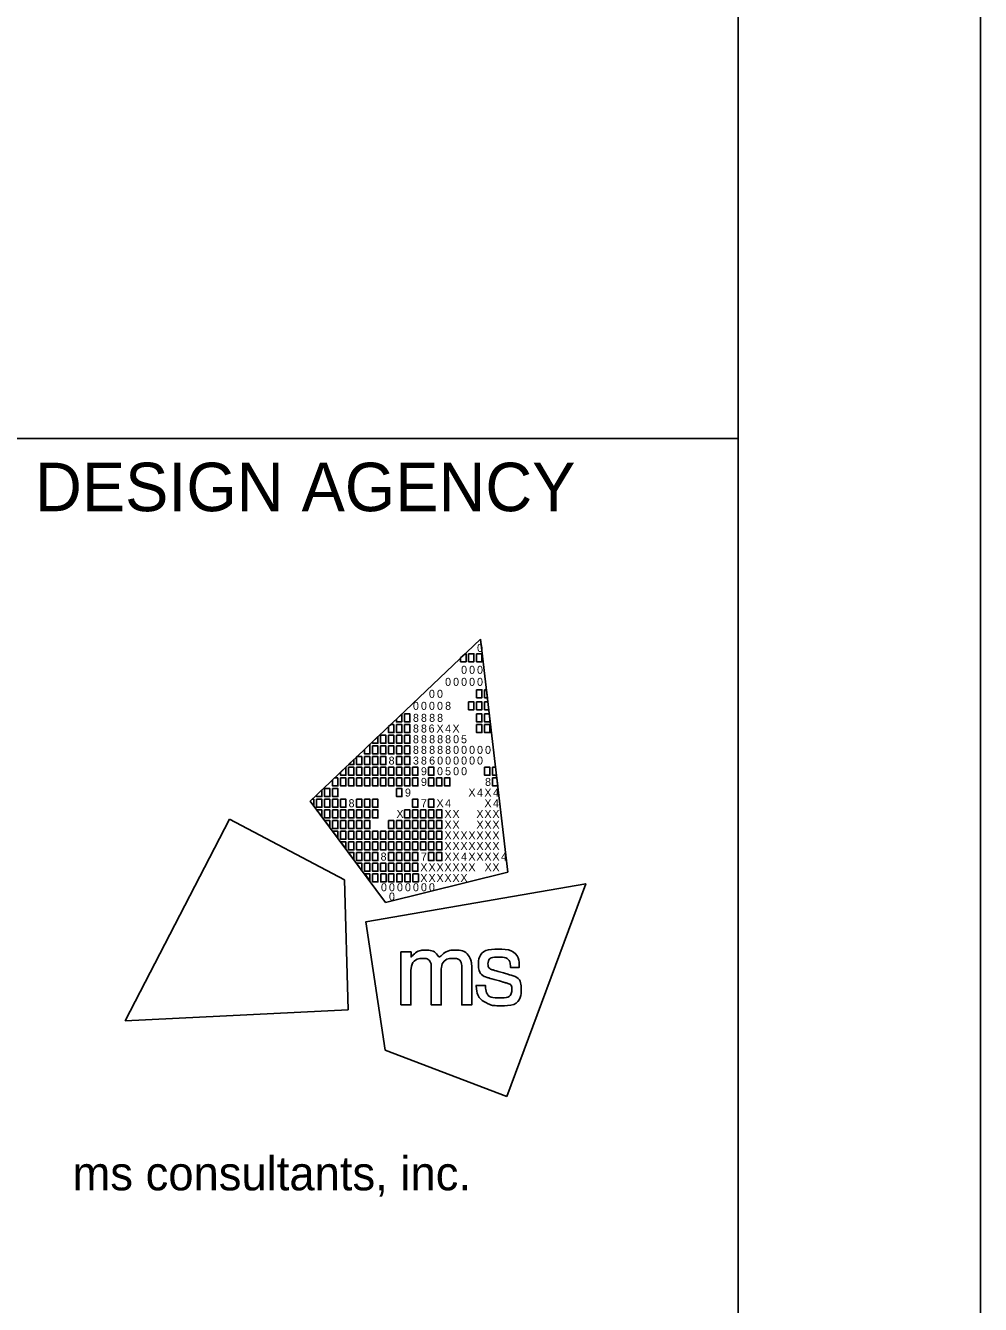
# Model space of a CAD drawing. Extents: x 0 to 65, y -0.7 to 22.
# Drawn here: x 32.03 to 34, y 2.714 to 5.352 of the extents above; entities that cross this region are included whole.
import ezdxf

# ---------------------------------------------------------------- set-up
doc = ezdxf.new("R2010")
doc.units = 0
for name, color, linetype in [('Default', 7, 'Continuous'), ('SH_Border', 7, 'Continuous'), ('SH_Cut_Line', 7, 'Continuous'), ('SH_Text', 7, 'Continuous')]:
    doc.layers.add(name, color=color, linetype=linetype)

msp = doc.modelspace()

# ---------------------------------------------------------------- linework, layer by layer
at = {"layer": 'Default'}
for p, q in [((32.6176, 3.7519), (32.9688, 4.0861)), ((32.9688, 4.0861), (32.9688, 4.0861)), ((32.9688, 4.0861), (33.0253, 3.6052)), ((32.773, 3.543), (32.6176, 3.7519)), ((33.0253, 3.6052), (32.773, 3.543))]:
    msp.add_line(p, q, dxfattribs=at)
for points in [[(32.9279, 4.0472), (32.9369, 4.0558), (32.939, 4.0558), (32.939, 4.0393), (32.9279, 4.0393)], [(32.9444, 4.0558), (32.9554, 4.0558), (32.9554, 4.0393), (32.9444, 4.0393)], [(32.9609, 4.0558), (32.9719, 4.0558), (32.9719, 4.0393), (32.9609, 4.0393)], [(32.9606, 3.9815), (32.9716, 3.9815), (32.9716, 3.965), (32.9606, 3.965)], [(32.9771, 3.9815), (32.9811, 3.9815), (32.983, 3.965), (32.9771, 3.965)], [(32.7954, 3.9211), (32.8064, 3.9316), (32.8064, 3.9154), (32.7954, 3.9154)], [(32.8123, 3.9319), (32.8233, 3.9319), (32.8233, 3.9154), (32.8123, 3.9154)], [(32.9442, 3.9567), (32.9552, 3.9567), (32.9552, 3.9402), (32.9442, 3.9402)], [(32.9606, 3.9567), (32.9716, 3.9567), (32.9716, 3.9402), (32.9606, 3.9402)], [(32.9606, 3.9319), (32.9716, 3.9319), (32.9716, 3.9154), (32.9606, 3.9154)], [(32.9771, 3.9567), (32.984, 3.9567), (32.9859, 3.9402), (32.9771, 3.9402)], [(32.9771, 3.9319), (32.9869, 3.9319), (32.9881, 3.9218), (32.9881, 3.9154), (32.9771, 3.9154)], [(32.7958, 3.9099), (32.8068, 3.9099), (32.8068, 3.8934), (32.7958, 3.8934)], [(32.8123, 3.9099), (32.8233, 3.9099), (32.8233, 3.8934), (32.8123, 3.8934)], [(32.9606, 3.9099), (32.9716, 3.9099), (32.9716, 3.8934), (32.9606, 3.8934)], [(32.9771, 3.9099), (32.9881, 3.9099), (32.9881, 3.8934), (32.9771, 3.8934)], [(32.7628, 3.8879), (32.7738, 3.8879), (32.7738, 3.8714), (32.7628, 3.8714)], [(32.7793, 3.8879), (32.7903, 3.8879), (32.7903, 3.8714), (32.7793, 3.8714)], [(32.7958, 3.8879), (32.8068, 3.8879), (32.8068, 3.8714), (32.7958, 3.8714)], [(32.8123, 3.8879), (32.8233, 3.8879), (32.8233, 3.8714), (32.8123, 3.8714)], [(32.7463, 3.8659), (32.7573, 3.8659), (32.7573, 3.8494), (32.7463, 3.8494)], [(32.7628, 3.8659), (32.7738, 3.8659), (32.7738, 3.8494), (32.7628, 3.8494)], [(32.7793, 3.8659), (32.7903, 3.8659), (32.7903, 3.8494), (32.7793, 3.8494)], [(32.7958, 3.8659), (32.8068, 3.8659), (32.8068, 3.8494), (32.7958, 3.8494)], [(32.8123, 3.8659), (32.8233, 3.8659), (32.8233, 3.8494), (32.8123, 3.8494)], [(32.7297, 3.8439), (32.7407, 3.8439), (32.7407, 3.8273), (32.7297, 3.8273)], [(32.7463, 3.8439), (32.7573, 3.8439), (32.7573, 3.8273), (32.7463, 3.8273)], [(32.7628, 3.8439), (32.7738, 3.8439), (32.7738, 3.8273), (32.7628, 3.8273)], [(32.7958, 3.8439), (32.8068, 3.8439), (32.8068, 3.8273), (32.7958, 3.8273)], [(32.8123, 3.8439), (32.8233, 3.8439), (32.8233, 3.8273), (32.8123, 3.8273)], [(32.6802, 3.7998), (32.6912, 3.7998), (32.6912, 3.7833), (32.6802, 3.7833)], [(32.6967, 3.8218), (32.7077, 3.8218), (32.7077, 3.8053), (32.6967, 3.8053)], [(32.6967, 3.7998), (32.7077, 3.7998), (32.7077, 3.7833), (32.6967, 3.7833)], [(32.7132, 3.8218), (32.7242, 3.8218), (32.7242, 3.8053), (32.7132, 3.8053)], [(32.7132, 3.7998), (32.7242, 3.7998), (32.7242, 3.7833), (32.7132, 3.7833)], [(32.7297, 3.8218), (32.7407, 3.8218), (32.7407, 3.8053), (32.7297, 3.8053)], [(32.7297, 3.7998), (32.7407, 3.7998), (32.7407, 3.7833), (32.7297, 3.7833)], [(32.7463, 3.8218), (32.7573, 3.8218), (32.7573, 3.8053), (32.7463, 3.8053)], [(32.7463, 3.7998), (32.7573, 3.7998), (32.7573, 3.7833), (32.7463, 3.7833)], [(32.7628, 3.8218), (32.7738, 3.8218), (32.7738, 3.8053), (32.7628, 3.8053)], [(32.7628, 3.7998), (32.7738, 3.7998), (32.7738, 3.7833), (32.7628, 3.7833)], [(32.7793, 3.8218), (32.7903, 3.8218), (32.7903, 3.8053), (32.7793, 3.8053)], [(32.7793, 3.7998), (32.7903, 3.7998), (32.7903, 3.7833), (32.7793, 3.7833)], [(32.7958, 3.8218), (32.8068, 3.8218), (32.8068, 3.8053), (32.7958, 3.8053)], [(32.7958, 3.7998), (32.8068, 3.7998), (32.8068, 3.7833), (32.7958, 3.7833)], [(32.8123, 3.8218), (32.8233, 3.8218), (32.8233, 3.8053), (32.8123, 3.8053)], [(32.8123, 3.7998), (32.8233, 3.7998), (32.8233, 3.7833), (32.8123, 3.7833)], [(32.8288, 3.8218), (32.8398, 3.8218), (32.8398, 3.8053), (32.8288, 3.8053)], [(32.8288, 3.7998), (32.8398, 3.7998), (32.8398, 3.7833), (32.8288, 3.7833)], [(32.8618, 3.8218), (32.8729, 3.8218), (32.8729, 3.8053), (32.8618, 3.8053)], [(32.8618, 3.7998), (32.8729, 3.7998), (32.8729, 3.7833), (32.8618, 3.7833)], [(32.8784, 3.7998), (32.8894, 3.7998), (32.8894, 3.7833), (32.8784, 3.7833)], [(32.8947, 3.7998), (32.9057, 3.7998), (32.9057, 3.7833), (32.8947, 3.7833)], [(32.9771, 3.8218), (32.9881, 3.8218), (32.9881, 3.8053), (32.9771, 3.8053)], [(32.9936, 3.8218), (32.9999, 3.8218), (33.0018, 3.8053), (32.9936, 3.8053)], [(32.9936, 3.7998), (33.0024, 3.7998), (33.0044, 3.7833), (32.9936, 3.7833)], [(32.6472, 3.7778), (32.6582, 3.7778), (32.6582, 3.7613), (32.6472, 3.7613)], [(32.6637, 3.7778), (32.6747, 3.7778), (32.6747, 3.7613), (32.6637, 3.7613)], [(32.7958, 3.7778), (32.8068, 3.7778), (32.8068, 3.7613), (32.7958, 3.7613)], [(32.6307, 3.7558), (32.6417, 3.7558), (32.6417, 3.7393), (32.6307, 3.7393)], [(32.6472, 3.7558), (32.6582, 3.7558), (32.6582, 3.7393), (32.6472, 3.7393)], [(32.6637, 3.7558), (32.6747, 3.7558), (32.6747, 3.7393), (32.6637, 3.7393)], [(32.6802, 3.7558), (32.6912, 3.7558), (32.6912, 3.7393), (32.6802, 3.7393)], [(32.7132, 3.7558), (32.7242, 3.7558), (32.7242, 3.7393), (32.7132, 3.7393)], [(32.7297, 3.7558), (32.7407, 3.7558), (32.7407, 3.7393), (32.7297, 3.7393)], [(32.7463, 3.7558), (32.7573, 3.7558), (32.7573, 3.7393), (32.7463, 3.7393)], [(32.8288, 3.7558), (32.8398, 3.7558), (32.8398, 3.7393), (32.8288, 3.7393)], [(32.8618, 3.7558), (32.8729, 3.7558), (32.8729, 3.7393), (32.8618, 3.7393)], [(32.6307, 3.7338), (32.6417, 3.7338), (32.6417, 3.72)], [(32.6472, 3.7338), (32.6582, 3.7338), (32.6582, 3.7173), (32.6472, 3.7173)], [(32.6637, 3.7338), (32.6747, 3.7338), (32.6747, 3.7173), (32.6637, 3.7173)], [(32.6802, 3.7338), (32.6912, 3.7338), (32.6912, 3.7173), (32.6802, 3.7173)], [(32.6967, 3.7338), (32.7077, 3.7338), (32.7077, 3.7173), (32.6967, 3.7173)], [(32.7132, 3.7338), (32.7242, 3.7338), (32.7242, 3.7173), (32.7132, 3.7173)], [(32.7297, 3.7338), (32.7407, 3.7338), (32.7407, 3.7173), (32.7297, 3.7173)], [(32.7463, 3.7338), (32.7573, 3.7338), (32.7573, 3.7173), (32.7463, 3.7173)], [(32.8123, 3.7338), (32.8233, 3.7338), (32.8233, 3.7173), (32.8123, 3.7173)], [(32.8288, 3.7338), (32.8398, 3.7338), (32.8398, 3.7173), (32.8288, 3.7173)], [(32.8453, 3.7338), (32.8563, 3.7338), (32.8563, 3.7173), (32.8453, 3.7173)], [(32.8618, 3.7338), (32.8729, 3.7338), (32.8729, 3.7173), (32.8618, 3.7173)], [(32.8784, 3.7338), (32.8894, 3.7338), (32.8894, 3.7173), (32.8784, 3.7173)], [(32.6472, 3.7117), (32.6582, 3.7117), (32.6582, 3.698)], [(32.6637, 3.7117), (32.6747, 3.7117), (32.6747, 3.6952), (32.6637, 3.6952)], [(32.6802, 3.7117), (32.6912, 3.7117), (32.6912, 3.6952), (32.6802, 3.6952)], [(32.6967, 3.7117), (32.7077, 3.7117), (32.7077, 3.6952), (32.6967, 3.6952)], [(32.7132, 3.7117), (32.7242, 3.7117), (32.7242, 3.6952), (32.7132, 3.6952)], [(32.7297, 3.7117), (32.7407, 3.7117), (32.7407, 3.6952), (32.7297, 3.6952)], [(32.7793, 3.7117), (32.7903, 3.7117), (32.7903, 3.6952), (32.7793, 3.6952)], [(32.7958, 3.7117), (32.8068, 3.7117), (32.8068, 3.6952), (32.7958, 3.6952)], [(32.8123, 3.7117), (32.8233, 3.7117), (32.8233, 3.6952), (32.8123, 3.6952)], [(32.8288, 3.7117), (32.8398, 3.7117), (32.8398, 3.6952), (32.8288, 3.6952)], [(32.8453, 3.7117), (32.8563, 3.7117), (32.8563, 3.6952), (32.8453, 3.6952)], [(32.8618, 3.7117), (32.8729, 3.7117), (32.8729, 3.6952), (32.8618, 3.6952)], [(32.8784, 3.7117), (32.8894, 3.7117), (32.8894, 3.6952), (32.8784, 3.6952)], [(32.6637, 3.6897), (32.6747, 3.6897), (32.6747, 3.676)], [(32.6747, 3.6897), (32.6747, 3.6897), (32.6747, 3.6897)], [(32.6802, 3.6897), (32.6912, 3.6897), (32.6912, 3.6732), (32.6802, 3.6732)], [(32.6802, 3.6677), (32.6912, 3.6677), (32.6912, 3.654)], [(32.6967, 3.6897), (32.7077, 3.6897), (32.7077, 3.6732), (32.6967, 3.6732)], [(32.6967, 3.6677), (32.7077, 3.6677), (32.7077, 3.6512), (32.6967, 3.6512)], [(32.7132, 3.6897), (32.7242, 3.6897), (32.7242, 3.6732), (32.7132, 3.6732)], [(32.7132, 3.6677), (32.7242, 3.6677), (32.7242, 3.6512), (32.7132, 3.6512)], [(32.7297, 3.6897), (32.7407, 3.6897), (32.7407, 3.6732), (32.7297, 3.6732)], [(32.7297, 3.6677), (32.7407, 3.6677), (32.7407, 3.6512), (32.7297, 3.6512)], [(32.7463, 3.6897), (32.7573, 3.6897), (32.7573, 3.6732), (32.7463, 3.6732)], [(32.7463, 3.6677), (32.7573, 3.6677), (32.7573, 3.6512), (32.7463, 3.6512)], [(32.7628, 3.6897), (32.7738, 3.6897), (32.7738, 3.6732), (32.7628, 3.6732)], [(32.7628, 3.6677), (32.7738, 3.6677), (32.7738, 3.6512), (32.7628, 3.6512)], [(32.7793, 3.6897), (32.7903, 3.6897), (32.7903, 3.6732), (32.7793, 3.6732)], [(32.7793, 3.6677), (32.7903, 3.6677), (32.7903, 3.6512), (32.7793, 3.6512)], [(32.7958, 3.6897), (32.8068, 3.6897), (32.8068, 3.6732), (32.7958, 3.6732)], [(32.7958, 3.6677), (32.8068, 3.6677), (32.8068, 3.6512), (32.7958, 3.6512)], [(32.8123, 3.6897), (32.8233, 3.6897), (32.8233, 3.6732), (32.8123, 3.6732)], [(32.8123, 3.6677), (32.8233, 3.6677), (32.8233, 3.6512), (32.8123, 3.6512)], [(32.8288, 3.6897), (32.8398, 3.6897), (32.8398, 3.6732), (32.8288, 3.6732)], [(32.8288, 3.6677), (32.8398, 3.6677), (32.8398, 3.6512), (32.8288, 3.6512)], [(32.8453, 3.6897), (32.8563, 3.6897), (32.8563, 3.6732), (32.8453, 3.6732)], [(32.8453, 3.6677), (32.8563, 3.6677), (32.8563, 3.6512), (32.8453, 3.6512)], [(32.8618, 3.6897), (32.8729, 3.6897), (32.8729, 3.6732), (32.8618, 3.6732)], [(32.8618, 3.6677), (32.8729, 3.6677), (32.8729, 3.6512), (32.8618, 3.6512)], [(32.8784, 3.6897), (32.8894, 3.6897), (32.8894, 3.6732), (32.8784, 3.6732)], [(32.8784, 3.6677), (32.8894, 3.6677), (32.8894, 3.6512), (32.8784, 3.6512)], [(32.7078, 3.6305), (32.6966, 3.6457), (32.7078, 3.6457)], [(32.7132, 3.6457), (32.7242, 3.6457), (32.7242, 3.6292), (32.7132, 3.6292)], [(32.7297, 3.6457), (32.7407, 3.6457), (32.7407, 3.6292), (32.7297, 3.6292)], [(32.7463, 3.6457), (32.7573, 3.6457), (32.7573, 3.6292), (32.7463, 3.6292)], [(32.7793, 3.6457), (32.7903, 3.6457), (32.7903, 3.6292), (32.7793, 3.6292)], [(32.7958, 3.6457), (32.8068, 3.6457), (32.8068, 3.6292), (32.7958, 3.6292)], [(32.8123, 3.6457), (32.8233, 3.6457), (32.8233, 3.6292), (32.8123, 3.6292)], [(32.8288, 3.6457), (32.8398, 3.6457), (32.8398, 3.6292), (32.8288, 3.6292)], [(32.8618, 3.6457), (32.8729, 3.6457), (32.8729, 3.6292), (32.8618, 3.6292)], [(32.8784, 3.6457), (32.8894, 3.6457), (32.8894, 3.6292), (32.8784, 3.6292)], [(32.724, 3.6082), (32.7132, 3.6237), (32.7242, 3.6237)], [(32.7297, 3.6237), (32.7407, 3.6237), (32.7407, 3.6072), (32.7297, 3.6072)], [(32.7463, 3.6237), (32.7573, 3.6237), (32.7573, 3.6072), (32.7463, 3.6072)], [(32.7628, 3.6237), (32.7738, 3.6237), (32.7738, 3.6072), (32.7628, 3.6072)], [(32.7793, 3.6237), (32.7903, 3.6237), (32.7903, 3.6072), (32.7793, 3.6072)], [(32.7958, 3.6237), (32.8068, 3.6237), (32.8068, 3.6072), (32.7958, 3.6072)], [(32.8123, 3.6237), (32.8233, 3.6237), (32.8233, 3.6072), (32.8123, 3.6072)], [(32.8288, 3.6237), (32.8398, 3.6237), (32.8398, 3.6072), (32.8288, 3.6072)], [(32.7302, 3.6017), (32.7407, 3.6017), (32.7408, 3.5875)], [(32.7463, 3.6017), (32.7573, 3.6017), (32.7573, 3.5852), (32.7463, 3.5852)], [(32.763, 3.6017), (32.774, 3.6017), (32.774, 3.5852), (32.763, 3.5852)], [(32.7794, 3.6017), (32.7904, 3.6017), (32.7904, 3.5852), (32.7794, 3.5852)], [(32.7961, 3.6017), (32.8071, 3.6017), (32.8071, 3.5852), (32.7961, 3.5852)], [(32.813, 3.6017), (32.824, 3.6017), (32.824, 3.5851), (32.813, 3.5851)], [(32.8296, 3.6017), (32.8407, 3.6017), (32.8407, 3.5851), (32.8296, 3.5851)]]:
    msp.add_lwpolyline(points, close=True, dxfattribs=at)
for points in [[(32.7903, 3.9099), (32.7836, 3.9099), (32.7793, 3.9058), (32.7793, 3.8934), (32.7903, 3.8934), (32.7903, 3.9099)], [(32.7573, 3.8849), (32.7463, 3.8744), (32.7463, 3.8714), (32.7573, 3.8714), (32.7573, 3.8849)], [(32.7407, 3.8691), (32.7297, 3.8587), (32.7297, 3.8494), (32.7407, 3.8494), (32.7407, 3.8691)], [(32.7077, 3.8377), (32.6968, 3.8273), (32.7077, 3.8273), (32.7077, 3.8377)], [(32.7242, 3.8439), (32.7142, 3.8439), (32.7132, 3.843), (32.7132, 3.8273), (32.7242, 3.8273), (32.7242, 3.8439)], [(32.6747, 3.7998), (32.6679, 3.7998), (32.6637, 3.7958), (32.6637, 3.7833), (32.6747, 3.7833), (32.6747, 3.7998)], [(32.6912, 3.822), (32.6802, 3.8115), (32.6802, 3.8053), (32.6912, 3.8053), (32.6912, 3.822)], [(32.6417, 3.7749), (32.6307, 3.7644), (32.6307, 3.7613), (32.6417, 3.7613), (32.6417, 3.7749)], [(32.6252, 3.7558), (32.6216, 3.7558), (32.6176, 3.7519), (32.6252, 3.7417), (32.6252, 3.7558)], [(32.4512, 3.7149), (32.2359, 3.2988), (32.6957, 3.3215), (32.6884, 3.5892), (32.4512, 3.7149)], [(33.0229, 3.1422), (33.1859, 3.5814), (32.7324, 3.5029), (32.7722, 3.2381), (33.0229, 3.1422)]]:
    msp.add_lwpolyline(points, dxfattribs=at)
for points in [[(32.8048, 3.3315), (32.8048, 3.3315), (32.8048, 3.4409), (32.8048, 3.4409), (32.8048, 3.4409), (32.8255, 3.4409), (32.8255, 3.4409), (32.8255, 3.4409), (32.8255, 3.4297), (32.8255, 3.4297), (32.8346, 3.4399), (32.8457, 3.4445), (32.8555, 3.4445), (32.8689, 3.4445), (32.8792, 3.4372), (32.8837, 3.4266), (32.8915, 3.4381), (32.905, 3.4446), (32.9166, 3.4446), (32.9325, 3.4446), (32.9451, 3.435), (32.9494, 3.4213), (32.9494, 3.4212), (32.9494, 3.4212), (32.9495, 3.4212), (32.9501, 3.419), (32.9507, 3.4172), (32.9507, 3.4071), (32.9507, 3.4071), (32.9507, 3.3314), (32.9507, 3.3314), (32.9507, 3.3314), (32.9303, 3.3314), (32.9303, 3.3314), (32.9303, 3.3314), (32.9303, 3.4048), (32.9303, 3.4048), (32.9303, 3.4201), (32.9219, 3.4274), (32.9111, 3.4274), (32.8995, 3.4274), (32.888, 3.4171), (32.888, 3.4001), (32.888, 3.4001), (32.888, 3.3315), (32.888, 3.3315), (32.888, 3.3315), (32.8674, 3.3315), (32.8674, 3.3315), (32.8674, 3.3315), (32.8674, 3.4059), (32.8674, 3.4059), (32.8674, 3.4203), (32.8588, 3.4274), (32.8497, 3.4274), (32.8384, 3.4274), (32.8254, 3.417), (32.8254, 3.3962), (32.8254, 3.3962), (32.8254, 3.3315), (32.8254, 3.3315), (32.8254, 3.3315), (32.8048, 3.3315), (32.8048, 3.3315)], [(32.9596, 3.3709), (32.9596, 3.3709), (32.9595, 3.3717), (32.9595, 3.3717), (32.9595, 3.3717), (32.9603, 3.3717), (32.9603, 3.3717), (32.9603, 3.3717), (32.9783, 3.3717), (32.9783, 3.3717), (32.9783, 3.3717), (32.9789, 3.3717), (32.9789, 3.3717), (32.9789, 3.3717), (32.979, 3.371), (32.979, 3.371), (32.9803, 3.3554), (32.9887, 3.346), (33.009, 3.346), (33.0273, 3.346), (33.0333, 3.3554), (33.0333, 3.3631), (33.0333, 3.3732), (33.0256, 3.3758), (33.0175, 3.378), (33.0175, 3.378), (32.987, 3.3867), (32.987, 3.3867), (32.9721, 3.3909), (32.9648, 3.4019), (32.9648, 3.4142), (32.9648, 3.4303), (32.9768, 3.4462), (33.0052, 3.4462), (33.0348, 3.4462), (33.0489, 3.4285), (33.0489, 3.4095), (33.0489, 3.4095), (33.0489, 3.4087), (33.0489, 3.4087), (33.0489, 3.4087), (33.0482, 3.4087), (33.0482, 3.4087), (33.0482, 3.4087), (33.0312, 3.4087), (33.0312, 3.4087), (33.0312, 3.4087), (33.0305, 3.4087), (33.0305, 3.4087), (33.0305, 3.4087), (33.0305, 3.4094), (33.0305, 3.4094), (33.0302, 3.4208), (33.0227, 3.43), (33.0056, 3.43), (32.9891, 3.43), (32.9843, 3.4218), (32.9843, 3.4157), (32.9843, 3.4108), (32.9869, 3.4059), (32.9959, 3.4033), (32.9959, 3.4033), (33.0255, 3.3948), (33.0255, 3.3948), (33.0462, 3.3889), (33.0527, 3.3777), (33.0527, 3.3639), (33.0527, 3.3462), (33.041, 3.3298), (33.0087, 3.3298), (32.9952, 3.3298), (32.9877, 3.3321), (32.9823, 3.3348), (32.9691, 3.3414), (32.961, 3.3536), (32.9596, 3.3709)]]:
    msp.add_open_spline(points, degree=3, dxfattribs=at)
at = {"layer": 'SH_Border'}
msp.add_line((32.75, 3.5), (32.75, 3.5), dxfattribs=at)
at = {"layer": 'SH_Cut_Line'}
msp.add_line((32, 4.5), (33.5, 4.5), dxfattribs=at)
msp.add_lwpolyline([(1.5, 21.5), (33.5, 21.5), (33.5, 0.5), (1.5, 0.5)], close=True, dxfattribs=at)
at = {"layer": 'SH_Text'}
msp.add_lwpolyline([(0, 0), (34, 0), (34, 22), (0, 22)], close=True, dxfattribs=at)

# ---------------------------------------------------------------- texts
at = {"layer": 'Default'}
for s, p in [('0', (32.9617, 4.0597)), ('0', (32.9288, 4.0145)), ('0', (32.9453, 4.0145)), ('0', (32.9617, 4.0145)), ('0', (32.8958, 3.9897)), ('0', (32.9123, 3.9897)), ('0', (32.9288, 3.9897)), ('0', (32.9453, 3.9897)), ('0', (32.9617, 3.9897)), ('0', (32.8625, 3.965)), ('0', (32.8791, 3.965)), ('0', (32.8295, 3.9402)), ('8', (32.8295, 3.9154)), ('0', (32.846, 3.9402)), ('8', (32.846, 3.9154)), ('0', (32.8625, 3.9402)), ('8', (32.8629, 3.9154)), ('0', (32.8791, 3.9402)), ('8', (32.8793, 3.9154)), ('8', (32.8958, 3.9402)), ('8', (32.8295, 3.8934)), ('8', (32.846, 3.8934)), ('6', (32.8618, 3.8934)), ('X', (32.8781, 3.8934)), ('4', (32.8959, 3.8934)), ('X', (32.911, 3.8934)), ('8', (32.8295, 3.8713)), ('8', (32.846, 3.8713)), ('8', (32.8629, 3.8713)), ('8', (32.8794, 3.8713)), ('8', (32.8958, 3.8713)), ('0', (32.9123, 3.8713)), ('5', (32.9287, 3.8713)), ('8', (32.8295, 3.8494)), ('8', (32.846, 3.8494)), ('8', (32.8629, 3.8494)), ('8', (32.8794, 3.8494)), ('8', (32.8958, 3.8494)), ('0', (32.9123, 3.8494)), ('0', (32.9288, 3.8494)), ('0', (32.9453, 3.8494)), ('0', (32.9617, 3.8494)), ('0', (32.9782, 3.8494)), ('8', (32.7793, 3.8273)), ('3', (32.8295, 3.8273)), ('8', (32.846, 3.8273)), ('6', (32.8629, 3.8273)), ('0', (32.8794, 3.8273)), ('0', (32.8958, 3.8273)), ('0', (32.9123, 3.8273)), ('0', (32.9288, 3.8273)), ('0', (32.9453, 3.8273)), ('0', (32.9617, 3.8273)), ('9', (32.846, 3.8053)), ('9', (32.846, 3.7833)), ('0', (32.8791, 3.8053)), ('5', (32.8958, 3.8053)), ('0', (32.9123, 3.8053)), ('0', (32.9288, 3.8053)), ('8', (32.9782, 3.7833)), ('9', (32.813, 3.7613)), ('X', (32.9439, 3.7613)), ('4', (32.9617, 3.7613)), ('X', (32.9769, 3.7613)), ('4', (32.9947, 3.7613)), ('8', (32.6967, 3.7393)), ('7', (32.846, 3.7393)), ('X', (32.8781, 3.7393)), ('4', (32.8959, 3.7393)), ('X', (32.9769, 3.7393)), ('4', (32.9947, 3.7393)), ('X', (32.7955, 3.7173)), ('X', (32.8945, 3.7173)), ('X', (32.911, 3.7173)), ('X', (32.9604, 3.7173)), ('X', (32.9769, 3.7173)), ('X', (32.9934, 3.7173)), ('X', (32.8945, 3.6952)), ('X', (32.911, 3.6952)), ('X', (32.9604, 3.6952)), ('X', (32.9769, 3.6952)), ('X', (32.9934, 3.6952)), ('X', (32.8945, 3.6732)), ('X', (32.8945, 3.6512)), ('X', (32.911, 3.6732)), ('X', (32.911, 3.6512)), ('X', (32.9275, 3.6732)), ('X', (32.9275, 3.6512)), ('X', (32.9439, 3.6732)), ('X', (32.9439, 3.6512)), ('X', (32.9604, 3.6732)), ('X', (32.9604, 3.6512)), ('X', (32.9769, 3.6732)), ('X', (32.9769, 3.6512)), ('X', (32.9934, 3.6732)), ('X', (32.9934, 3.6512)), ('8', (32.7628, 3.6292)), ('7', (32.846, 3.6292)), ('X', (32.8945, 3.6292)), ('X', (32.911, 3.6292)), ('4', (32.9288, 3.6292)), ('X', (32.9439, 3.6292)), ('X', (32.9604, 3.6292)), ('X', (32.9769, 3.6292)), ('X', (32.9934, 3.6292)), ('4', (33.0112, 3.6292)), ('X', (32.8447, 3.6072)), ('X', (32.8616, 3.6072)), ('X', (32.8781, 3.6072)), ('X', (32.8945, 3.6072)), ('X', (32.911, 3.6072)), ('X', (32.9275, 3.6072)), ('X', (32.9439, 3.6072)), ('X', (32.9772, 3.6072)), ('X', (32.9934, 3.6072)), ('X', (32.8447, 3.5851)), ('X', (32.8616, 3.5851)), ('X', (32.8781, 3.5851)), ('X', (32.8945, 3.5851)), ('X', (32.911, 3.5851)), ('X', (32.9275, 3.5851)), ('0', (32.7635, 3.5659)), ('0', (32.78, 3.5659)), ('0', (32.78, 3.5467)), ('0', (32.7965, 3.5659)), ('0', (32.813, 3.5659)), ('0', (32.8295, 3.5659)), ('0', (32.846, 3.5659)), ('0', (32.8625, 3.5659))]:
    msp.add_text(s, height=0.0165, rotation=360, dxfattribs=at).set_placement(p)
at = {"layer": 'SH_Border'}
msp.add_text('DESIGN AGENCY', height=0.1, dxfattribs=at).set_placement((32.05, 4.35))
at = {"layer": 'SH_Cut_Line'}
msp.add_text('ms consultants, inc.', height=0.07, rotation=360, dxfattribs=at).set_placement((32.1273, 2.9489))

doc.saveas('drawing.dxf')
